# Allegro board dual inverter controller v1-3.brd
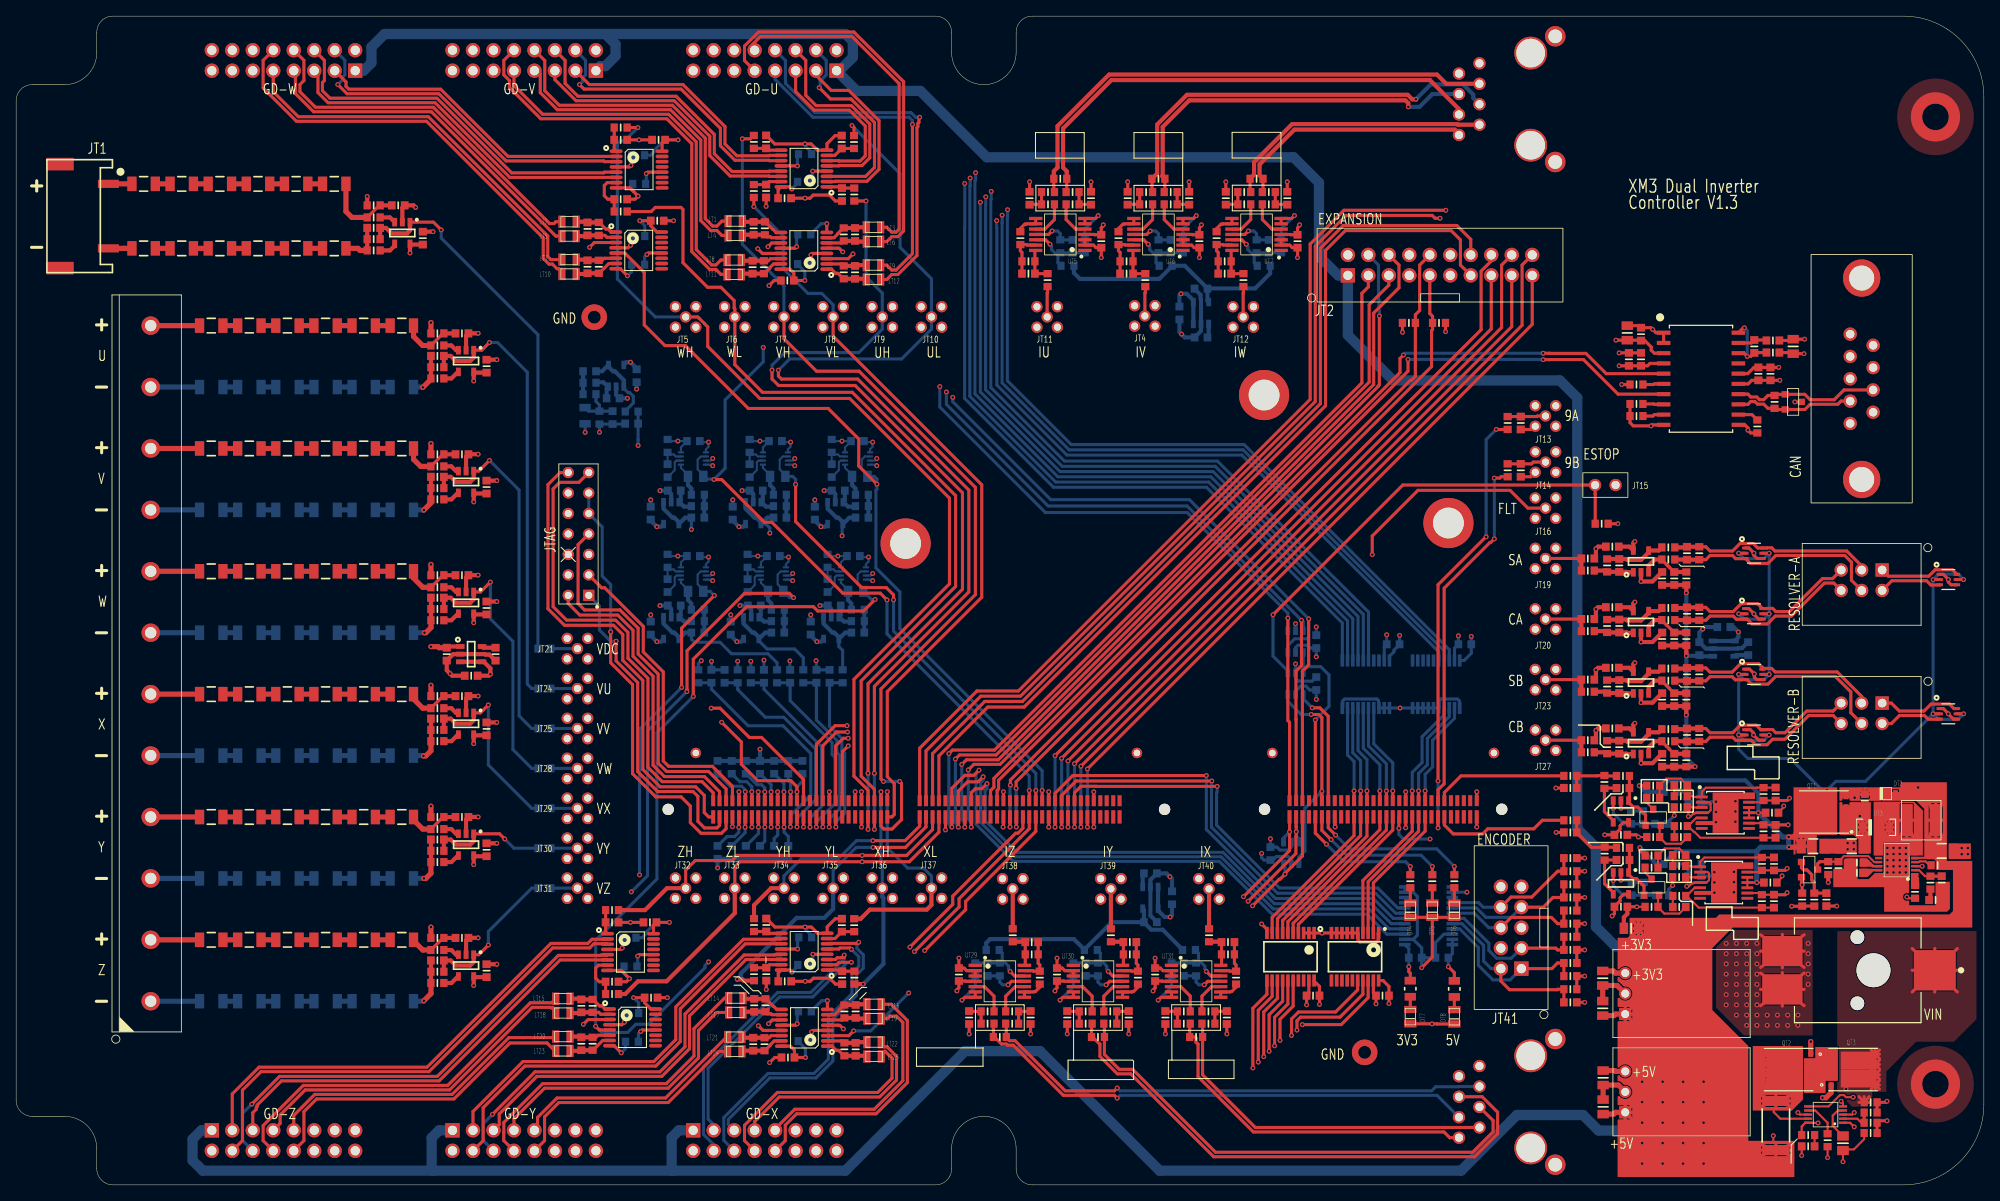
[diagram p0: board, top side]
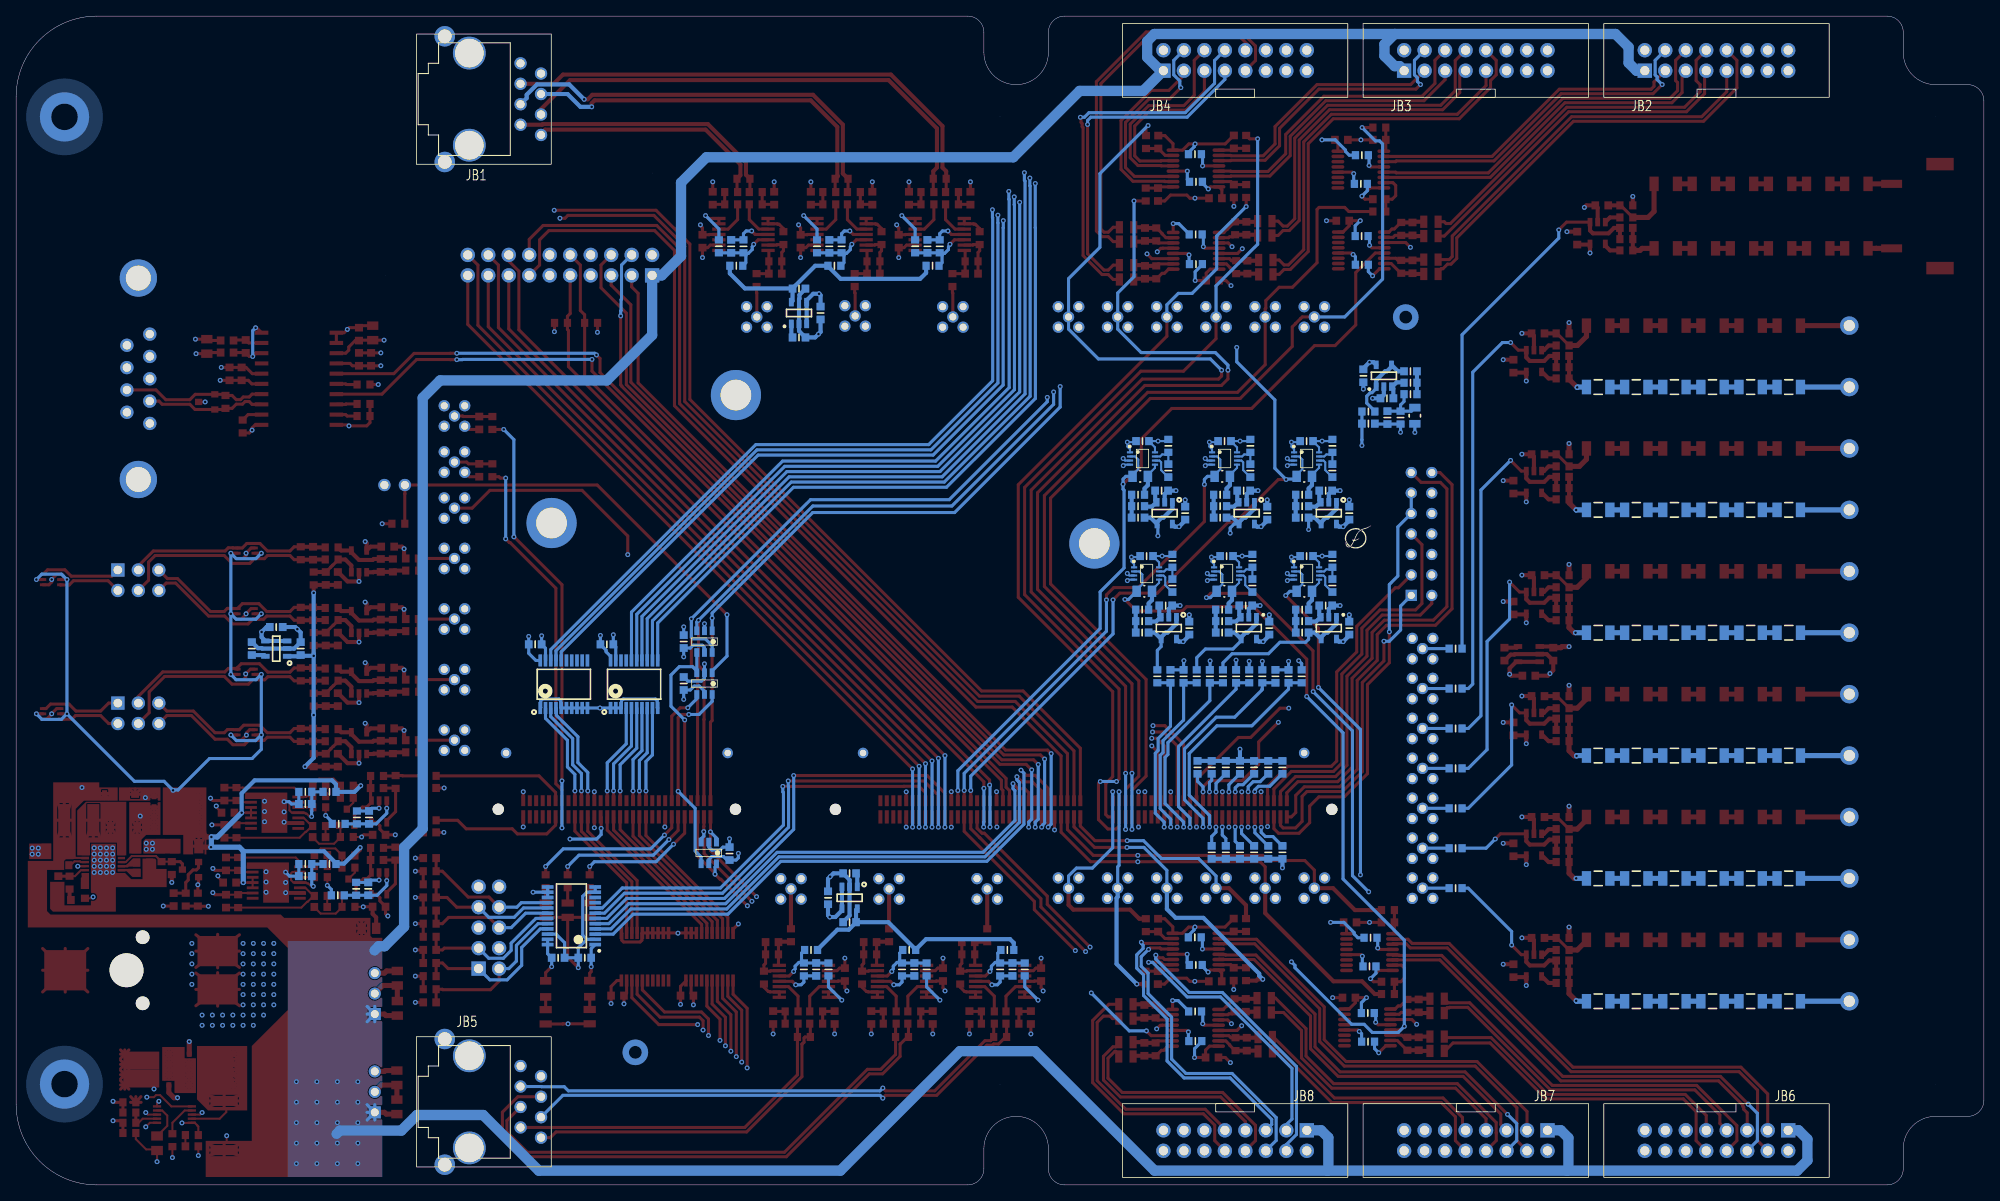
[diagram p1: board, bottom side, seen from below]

Outline 244 x 145 mm; copper layers: TOP, GND1, LAYER3, PWR, PWR2, BOTTOM. Coordinates in mm from the lower left corner of the outline.
Outline path: 0,134.5 arc(0.59,135.91) 2,136.5 6,136.5 arc(8.83,137.67) 10,140.5 10,143 arc(10.59,144.41) 12,145 114,145 arc(115.41,144.41) 116,143 116,140.5 arc(120,136.5) 124,140.5 124,143 arc(124.59,144.41) 126,145 234,145 arc(241.07,142.07) 244,135 244,10 arc(241.07,2.93) 234,0 126,0 arc(124.59,0.59) 124,2 124,4.5 arc(120,8.5) 116,4.5 116,2 arc(115.41,0.59) 114,0 12,0 arc(10.59,0.59) 10,2 10,4.5 arc(8.83,7.33) 6,8.5 2,8.5 arc(0.59,9.09) 0,10.5 0,134.5

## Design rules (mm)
constraint set DEFAULT: min track width 0.127
net group CANA: nets CANA-H CANA-L
net group COS-A-: nets COS-A-N COS-A-P
net group COS-B-: nets COS-B-N COS-B-P
net group CURRENT-U: nets CURRENT-U_N CURRENT-U_P
net group CURRENT-V: nets CURRENT-V_N CURRENT-V_P
net group CURRENT-W: nets CURRENT-W_N CURRENT-W_P
net group CURRENT-X: nets CURRENT-Z_N CURRENT-Z_P
net group CURRENT-Y: nets CURRENT-Y_N CURRENT-Y_P
net group CURRENT-Z: nets CURRENT-X_N CURRENT-X_P
net group EXC-A-: nets EXC-A-N EXC-A-P
net group EXC-B-: nets EXC-B-N EXC-B-P
net group SIN-A-: nets SIN-A-N SIN-A-P
net group SIN-B-: nets SIN-B-N SIN-B-P
net group U-FAULT-: nets U-FAULT-N U-FAULT-P
net group U-RTD-: nets U-RTD-N U-RTD-P
net group UHS-PWM-: nets UHS-PWM-N UHS-PWM-P
net group ULS-PWM-: nets ULS-PWM-N ULS-PWM-P
net group V-FAULT-: nets V-FAULT-N V-FAULT-P
net group V-RTD-: nets V-RTD-N V-RTD-P
net group VHS-PWM-: nets VHS-PWM-N VHS-PWM-P
net group VLS-PWM-: nets VLS-PWM-N VLS-PWM-P
net group W-FAULT-: nets W-FAULT-N W-FAULT-P
net group W-RTD-: nets W-RTD-N W-RTD-P
net group WHS-PWM-: nets WHS-PWM-N WHS-PWM-P
net group WLS-PWM-: nets WLS-PWM-N WLS-PWM-P
net group X-FAULT-: nets X-FAULT-N X-FAULT-P
net group X-RTD-: nets X-RTD-N X-RTD-P
net group XHS-PWM-: nets XHS-PWM-N XHS-PWM-P
net group XLS-PWM-: nets XLS-PWM-N XLS-PWM-P
net group Y-FAULT-: nets Y-FAULT-N Y-FAULT-P
net group Y-RTD-: nets Y-RTD-N Y-RTD-P
net group YHS-PWM-: nets YHS-PWM-N YHS-PWM-P
net group YLS-PWM-: nets YLS-PWM-N YLS-PWM-P
net group Z-FAULT-: nets Z-FAULT-N Z-FAULT-P
net group Z-RTD-: nets Z-RTD-N Z-RTD-P
net group ZHS-PWM-: nets ZHS-PWM-N ZHS-PWM-P
net group ZLS-PWM-: nets ZLS-PWM-N ZLS-PWM-P
net group VBM: nets N4927466 N4927468 N4927470 N4927528 N4927530 N4932900 N4932902 N4932904 N4932954 N4932956 V_V- V_Y-

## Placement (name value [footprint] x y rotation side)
CB1  100pF  [CAPC1608X90N]  131 116.44 270 bottom
CB2  100pF  [CAPC1608X90N]  143.17 116.44 270 bottom
CB3  100pF  [CAPC1608X90N]  155.34 116.44 270 bottom
CB4  0.1uF  [CAPC1608X87N]  146.92 111.19 180 bottom
CB5  0.1uF  [CAPC1608X87N]  144.25 108.17 270 bottom
CB6  0.1uF  [CAPC1608X87N]  146.92 105.14 180 bottom
CB7  10000pF  [CAPC1608X90N]  71.1 100.94 0 bottom
CB8  0.1uF  [CAPC1608X87N]  76.94 100.38 270 bottom
CB9  4700pF  [CAPC1608X90N]  74.02 97.59 180 bottom
CB10  100pF  [CAPC1608X90N]  73.96 95.19 90 bottom
CB11  4700pF  [CAPC1608X87N]  76.32 94.44 180 bottom
CB12  0.1uF  [CAPC1608X87N]  83.98 92.27 0 bottom
CB13  0.1uF  [CAPC1608X87N]  94.16 92.27 0 bottom
CB14  0.1uF  [CAPC1608X87N]  104.33 92.27 0 bottom
CB15  10000pF  [CAPC1608X90N]  80.78 88.61 270 bottom
CB16  10000pF  [CAPC1608X90N]  90.96 88.61 270 bottom
CB17  10000pF  [CAPC1608X90N]  101.13 88.61 270 bottom
CB18  10000pF  [CAPC1608X90N]  81.61 86.13 0 bottom
CB19  10000pF  [CAPC1608X90N]  91.78 86.13 0 bottom
CB20  10000pF  [CAPC1608X90N]  101.96 86.13 0 bottom
CB21  0.1uF  [CAPC1608X87N]  78.69 83.34 90 bottom
CB22  0.1uF  [CAPC1608X87N]  88.86 83.34 90 bottom
CB23  0.1uF  [CAPC1608X87N]  99.04 83.34 90 bottom
CB24  10000pF  [CAPC1608X90N]  84.53 82.78 180 bottom
CB25  10000pF  [CAPC1608X90N]  94.71 82.78 180 bottom
CB26  10000pF  [CAPC1608X90N]  104.88 82.78 180 bottom
CB27  0.1uF  [CAPC1608X87N]  83.98 78.01 0 bottom
CB28  0.1uF  [CAPC1608X87N]  93.9 78.01 0 bottom
CB29  0.1uF  [CAPC1608X87N]  103.82 78.01 0 bottom
CB30  10000pF  [CAPC1608X90N]  80.78 74.35 270 bottom
CB31  10000pF  [CAPC1608X90N]  90.7 74.35 270 bottom
CB32  10000pF  [CAPC1608X90N]  100.62 74.35 270 bottom
CB33  10000pF  [CAPC1608X90N]  81.61 71.87 0 bottom
CB34  10000pF  [CAPC1608X90N]  91.53 71.87 0 bottom
CB35  10000pF  [CAPC1608X90N]  101.45 71.87 0 bottom
CB36  0.1uF  [CAPC1608X87N]  211.74 69.21 180 bottom
CB37  0.1uF  [CAPC1608X87N]  78.69 69.08 90 bottom
CB38  0.1uF  [CAPC1608X87N]  88.61 69.08 90 bottom
CB39  0.1uF  [CAPC1608X87N]  98.53 69.08 90 bottom
CB40  10000pF  [CAPC1608X90N]  84.53 68.52 180 bottom
CB41  10000pF  [CAPC1608X90N]  94.45 68.52 180 bottom
CB42  10000pF  [CAPC1608X90N]  104.37 68.52 180 bottom
CB43  0.1uF  [CAPC1608X87N]  161.22 67.41 90 bottom
CB44  0.1uF  [CAPC1608X87N]  170.75 67.06 180 bottom
CB45  0.1uF  [CAPC1608X87N]  179.64 67.06 180 bottom
CB46  0.1uF  [CAPC1608X87N]  208.72 66.53 90 bottom
CB47  0.1uF  [CAPC1608X87N]  214.77 66.53 90 bottom
CB48  4700pF  [CAPC1608X87N]  86.22 63.1 90 bottom
CB49  4700pF  [CAPC1608X87N]  87.85 63.1 90 bottom
CB50  4700pF  [CAPC1608X87N]  92.73 63.1 90 bottom
CB51  4700pF  [CAPC1608X87N]  95.98 63.1 90 bottom
CB52  4700pF  [CAPC1608X87N]  99.24 63.1 90 bottom
CB53  4700pF  [CAPC1608X87N]  100.86 63.1 90 bottom
CB54  0.1uF  [CAPC1608X87N]  161.22 62.2 90 bottom
CB55  0.27 uF  [CAPC1608X90N]  86.98 51.8 90 bottom
CB56  0.27 uF  [CAPC1608X90N]  88.74 51.8 90 bottom
CB57  0.27 uF  [CAPC1608X90N]  90.49 51.8 90 bottom
CB58  0.27 uF  [CAPC1608X90N]  92.24 51.8 90 bottom
CB59  0.27 uF  [CAPC1608X90N]  94 51.8 90 bottom
CB60  0.27 uF  [CAPC1608X90N]  95.75 51.8 90 bottom
CB61  0.27 uF  [CAPC1608X90N]  97.51 51.8 90 bottom
CB62  0.27 uF  [CAPC1608X90N]  86.98 41.26 270 bottom
CB63  0.27 uF  [CAPC1608X90N]  88.74 41.26 270 bottom
CB64  0.27 uF  [CAPC1608X90N]  90.49 41.26 270 bottom
CB65  0.27 uF  [CAPC1608X90N]  92.24 41.26 270 bottom
CB66  0.27 uF  [CAPC1608X90N]  94 41.26 270 bottom
CB67  0.27 uF  [CAPC1608X90N]  95.75 41.26 270 bottom
CB68  0.1uF  [CAPC1608X87N]  155.54 41.1 90 bottom
CB69  0.1uF  [CAPC1608X87N]  140.65 38.65 0 bottom
CB70  0.1uF  [CAPC1608X87N]  143.33 35.62 90 bottom
CB71  0.1uF  [CAPC1608X87N]  140.65 32.59 0 bottom
CB72  0.1uF  [CAPC1608X87N]  173.49 28.18 0 bottom
CB73  0.1uF  [CAPC1608X87N]  176.79 28.18 180 bottom
CB74  100pF  [CAPC1608X90N]  120.46 26.73 90 bottom
CB75  100pF  [CAPC1608X90N]  132.63 26.73 90 bottom
CB76  100pF  [CAPC1608X90N]  144.79 26.73 90 bottom
CB79  0.1uF  [CAPC1608X87N]  208.14 38.3 0 bottom
CB81  0.1uF  [CAPC1608X87N]  208.14 47.26 0 bottom
CB83  0.1uF  [CAPC1608X87N]  200.34 36.73 90 bottom
CB84  0.1uF  [CAPC1608X87N]  200.24 45.59 90 bottom
CT1  100pF  [CAPC1608X90N]  74.97 129.65 0 top
CT2  0.1uF  [CAPC1608X87N]  79.66 129.65 180 top
CT3  100pF  [CAPC1608X90N]  93 129.4 90 top
CT4  100pF  [CAPC1608X90N]  102.37 129.38 90 top
CT5  100pF  [CAPC1608X90N]  93 123.3 270 top
CT6  100pF  [CAPC1608X90N]  102.41 122.87 270 top
CT7  0.1uF  [CAPC1608X87N]  95.29 122.41 0 top
CT8  100pF  [CAPC1608X90N]  125.67 122.41 90 top
CT9  100pF  [CAPC1608X90N]  133.29 122.41 270 top
CT10  100pF  [CAPC1608X90N]  137.83 122.41 90 top
CT11  100pF  [CAPC1608X90N]  145.45 122.41 270 top
CT12  100pF  [CAPC1608X90N]  150 122.41 90 top
CT13  100pF  [CAPC1608X90N]  157.62 122.41 270 top
CT14  100pF  [CAPC1608X90N]  74.97 122.28 0 top
CT15  4700pF  [CAPC1608X90N]  47.38 121.52 180 top
CT16  0.1uF  [CAPC1608X87N]  79.5 119.62 0 top
CT17  4700pF  [CAPC1608X90N]  44.33 118.73 0 top
CT18  27pF  [CAPC1608X90N]  91.45 118.68 90 top
CT19  27pF  [CAPC1608X90N]  70.85 118.6 90 top
CT20  27pF  [CAPC1608X90N]  104.02 117.92 90 top
CT21  0.1uF  [CAPC1608X87N]  50.43 117.46 90 top
CT22  0.1uF  [CAPC1608X87N]  134.56 117.08 270 top
CT23  0.1uF  [CAPC1608X87N]  146.72 117.08 270 top
CT24  0.1uF  [CAPC1608X87N]  158.89 117.08 270 top
CT25  27pF  [CAPC1608X90N]  70.85 113.9 270 top
CT26  27pF  [CAPC1608X90N]  91.32 113.85 270 top
CT27  27pF  [CAPC1608X90N]  104.02 113.22 270 top
CT28  100pF  [CAPC1608X90N]  125.52 113.05 0 top
CT29  100pF  [CAPC1608X90N]  137.69 113.05 0 top
CT30  100pF  [CAPC1608X90N]  149.86 113.05 0 top
CT31  0.1uF  [CAPC1608X87N]  95.63 112.2 180 top
CT33  0.1uF  [CAPC1608X87N]  199.98 102.42 90 top
CT34  10000pF  [CAPC1608X90N]  55.28 105.64 180 top
CT35  10000pF  [CAPC1608X90N]  52.24 102.84 0 top
CT36  0.1uF  [CAPC1608X87N]  58.33 101.57 90 top
CT37  1000 pF  [CAPC1608X90N]  186.57 94.52 270 top
CT39  10000pF  [CAPC1608X90N]  55.28 90.64 180 top
CT40  1000 pF  [CAPC1608X90N]  186.57 88.65 270 top
CT41  10000pF  [CAPC1608X90N]  52.24 87.84 0 top
CT42  0.1uF  [CAPC1608X87N]  58.33 86.57 90 top
CT43  0.1uF  [CAPC1608X87N]  197.93 79.18 180 top
CT44  47pF  [CAPC1608X87N]  207.18 78.36 90 top
CT45  1000 pF  [CAPC1608X90N]  194.89 77.71 0 top
CT46  330pF  [CAPC1608X87N]  198.78 76.85 270 top
CT47  10000pF  [CAPC1608X90N]  55.28 75.64 180 top
CT48  0.1uF  [CAPC1608X87N]  204.1 75.23 90 top
CT49  330pF  [CAPC1608X87N]  205.6 75.23 90 top
CT50  10000pF  [CAPC1608X90N]  52.24 72.84 0 top
CT51  0.1uF  [CAPC1608X87N]  197.93 71.66 180 top
CT52  0.1uF  [CAPC1608X87N]  58.33 71.57 90 top
CT53  47pF  [CAPC1608X87N]  207.18 70.85 90 top
CT54  1000 pF  [CAPC1608X90N]  194.89 70.2 0 top
CT55  330pF  [CAPC1608X87N]  198.78 69.34 270 top
CT56  0.1uF  [CAPC1608X87N]  204.1 67.72 90 top
CT57  330pF  [CAPC1608X87N]  205.6 67.72 90 top
CT58  0.1uF  [CAPC1608X87N]  53.4 65.85 270 top
CT59  0.1uF  [CAPC1608X87N]  59.45 65.85 270 top
CT60  0.1uF  [CAPC1608X87N]  197.93 64.15 180 top
CT61  47pF  [CAPC1608X87N]  207.18 63.33 90 top
CT62  0.1uF  [CAPC1608X87N]  56.42 63.17 180 top
CT63  1000 pF  [CAPC1608X90N]  194.89 62.68 0 top
CT64  330pF  [CAPC1608X87N]  198.78 61.82 270 top
CT65  10000pF  [CAPC1608X90N]  55.28 60.64 180 top
CT66  0.1uF  [CAPC1608X87N]  204.1 60.2 90 top
CT67  330pF  [CAPC1608X87N]  205.6 60.2 90 top
CT68  10000pF  [CAPC1608X90N]  52.24 57.84 0 top
CT69  0.1uF  [CAPC1608X87N]  197.93 56.63 180 top
CT70  0.1uF  [CAPC1608X87N]  58.33 56.57 90 top
CT71  47pF  [CAPC1608X87N]  207.18 55.82 90 top
CT72  1000 pF  [CAPC1608X90N]  194.89 55.17 0 top
CT73  330pF  [CAPC1608X87N]  198.78 54.3 270 top
CT74  0.1uF  [CAPC1608X87N]  204.1 52.69 90 top
CT75  330pF  [CAPC1608X87N]  205.6 52.69 90 top
CT81  10000pF  [CAPC1608X90N]  55.28 45.64 180 top
CT86  10000pF  [CAPC1608X90N]  52.24 42.84 0 top
CT87  10 uF  [CAPC3216X180N]  222.84 42.02 0 top
CT88  4.7uF  [CAPC3216X180N]  227.62 42.02 180 top
CT89  0.1uF  [CAPC1608X87N]  58.33 41.57 90 top
CT90  4.7uF  [CAPC3216X180N]  238.77 41.44 0 top
CT91  1000 pF  [CAPC1608X90N]  192.72 40.54 0 top
CT95  0.1uF  [CAPC1608X87N]  217.53 37.51 0 top
CT97  0.1uF  [CAPC1608X90N]  228.25 38.72 0 top
CT98  56 pF  [CAPC1608X90N]  238.77 37.5 90 top
CT99  1000 pF  [CAPC1608X90N]  192.72 35.66 0 top
CT100  100pF  [CAPC1608X90N]  224.47 35.39 270 top
CT103  1000 pF  [CAPC1608X87N]  192.72 43.73 0 top
CT104  1000pF  [CAPC1608X90N]  238.01 35.34 0 top
CT106  1000 pF  [CAPC1608X90N]  192.72 34.03 0 top
CT107  100pF  [CAPC1608X90N]  73.89 32.57 0 top
CT108  0.1uF  [CAPC1608X87N]  78.59 32.57 180 top
CT109  100pF  [CAPC1608X90N]  93.02 32.24 90 top
CT110  100pF  [CAPC1608X90N]  102.39 32.22 90 top
CT111  10uF  [CAPC2012X135N]  200.26 31.83 180 top
CT112  10000pF  [CAPC1608X90N]  55.28 30.64 180 top
CT113  100pF  [CAPC1608X90N]  125.93 30.12 180 top
CT114  100pF  [CAPC1608X90N]  138.1 30.12 180 top
CT115  100pF  [CAPC1608X90N]  150.27 30.12 180 top
CT116  1000 pF  [CAPC1608X90N]  192.72 29.15 0 top
CT117  10000pF  [CAPC1608X90N]  52.24 27.84 0 top
CT118  1000 pF  [CAPC1608X90N]  192.72 27.53 0 top
CT119  0.1uF  [CAPC1608X87N]  58.33 26.57 90 top
CT120  100pF  [CAPC1608X90N]  93.02 26.14 270 top
CT121  0.1uF  [CAPC1608X87N]  116.9 26.09 90 top
CT122  0.1uF  [CAPC1608X87N]  129.07 26.09 90 top
CT123  0.1uF  [CAPC1608X87N]  141.24 26.09 90 top
CT124  100pF  [CAPC1608X90N]  102.43 25.71 270 top
CT125  10uF  [CAPC2012X135N]  196.73 25.64 270 top
CT126  0.1uF  [CAPC1608X87N]  95.31 25.25 0 top
CT127  100pF  [CAPC1608X90N]  73.89 25.2 0 top
CT128  0.1uF  [CAPC1608X87N]  160.82 23.48 180 top
CT129  0.1uF  [CAPC1608X87N]  169.43 23.48 180 top
CT130  0.1uF  [CAPC1608X87N]  78.73 23.22 0 top
CT131  1000 pF  [CAPC1608X90N]  192.72 22.64 0 top
CT132  27pF  [CAPC1608X90N]  91.53 22.28 90 top
CT133  27pF  [CAPC1608X90N]  70.08 22.21 90 top
CT134  10uF  [CAPC2012X135N]  196.73 21.9 90 top
CT135  27pF  [CAPC1608X90N]  104.1 21.52 90 top
CT136  100pF  [CAPC1608X90N]  118.17 20.76 90 top
CT137  100pF  [CAPC1608X90N]  125.79 20.76 270 top
CT138  100pF  [CAPC1608X90N]  130.34 20.76 90 top
CT139  100pF  [CAPC1608X90N]  137.96 20.76 270 top
CT140  100pF  [CAPC1608X90N]  142.51 20.76 90 top
CT141  100pF  [CAPC1608X90N]  150.13 20.76 270 top
CT142  27pF  [CAPC1608X90N]  70.08 17.51 270 top
CT143  27pF  [CAPC1608X90N]  91.4 17.45 270 top
CT144  27pF  [CAPC1608X90N]  104.1 16.82 270 top
CT145  0.1uF  [CAPC1608X87N]  95.71 15.8 180 top
CT146  10uF  [CAPC2012X135N]  196.79 13.28 270 top
CT147  10uF  [CAPC2012X135N]  196.79 9.68 90 top
CT148  0.022uF  [CAPC2012X70N]  226.53 5.16 270 top
CT149  4700pF  [CAPC1608X90N]  222.21 4.78 180 top
CT150  0.1uF  [CAPC1608X87N]  201.49 105.55 90 top
CT151  0.1uF  [CAPC1608X87N]  217.54 100.62 270 top
CT152  0.1uF  [CAPC1608X87N]  215.53 104.02 270 top
CT153  10uF  [CAPC2012X135N]  199.78 105.7 90 top
CT154  10uF  [CAPC2012X135N]  220.35 104.02 270 top
CT155  10000pF  [CAPC1608X90N]  216.04 100.62 270 top
CT156  10000pF  [CAPC1608X90N]  201.48 102.42 90 top
CT157  18pF  [CAPC1608X90N]  217.98 39.82 270 top
CT158  18pF  [CAPC1608X90N]  217.97 35.2 90 top
CT159  1000 pF  [CAPC1608X90N]  199.25 40.31 0 top
CT160  0.1uF  [CAPC1608X87N]  198.99 34.51 0 top
CT161  0.1uF  [CAPC1608X87N]  217.73 46.17 0 top
CT162  18pF  [CAPC1608X90N]  218.18 48.49 270 top
CT163  0.1uF  [CAPC1608X87N]  198.99 43.43 0 top
CT164  1000 pF  [CAPC1608X87N]  192.72 49.24 0 top
CT165  1000 pF  [CAPC1608X90N]  199.25 49.23 0 top
CT166  18pF  [CAPC1608X90N]  218.17 43.87 90 top
CT167  10000pF  [CAPC1608X90N]  206.42 49.59 0 top
CT168  10000pF  [CAPC1608X90N]  206.43 43.14 0 top
CT169  10000pF  [CAPC1608X90N]  206.21 40.93 0 top
CT170  10000pF  [CAPC1608X90N]  206.23 34.48 0 top
DT2  CUS520,H3F  [SOD-323-AC]  231.91 48.55 180 top
DT3  NTS260ESFT3G  [SOD-123F-AC]  230.64 44.36 180 top
DT4  LH R974-LP-1  [D_0805]  172.88 34.08 270 top
DT5  LTST-C171KSKT  [D_0805]  175.61 34.08 270 top
DT6  LG R971-KN-1  [D_0805]  178.34 34.08 270 top
DT7  LTST-C171GKT  [D_0805]  172.88 20.87 270 top
DT8  LTST-C171GKT  [D_0805]  178.34 20.85 270 top
DT9  CPDT-12V  [SOT-23-3-D]  222.23 94.75 90 top
DT10  BAS40DW-04-TP  [SOT363_NEX]  215.49 55.82 0 top
DT11  BAS40DW-04-TP  [SOT363_NEX]  215.49 63.33 0 top
DT12  BAS40DW-04-TP  [SOT363_NEX]  239.59 58.44 0 top
DT13  BAS40DW-04-TP  [SOT363_NEX]  215.49 70.85 0 top
DT14  BAS40DW-04-TP  [SOT363_NEX]  215.49 78.36 0 top
DT15  BAS40DW-04-TP  [SOT363_NEX]  239.59 75.1 0 top
JB1  A-2014-2S-4-N-R  [RJ45_VERT_SHIELD_CON]  181.45 139.14 90 bottom
JB2  SBH11-PBPC-D08-ST-BK  [CON_2X8_SHROUDED_CORRECTED]  42.04 138.23 90 bottom
JB3  SBH11-PBPC-D08-ST-BK  [CON_2X8_SHROUDED_CORRECTED]  71.89 138.23 90 bottom
JB4  SBH11-PBPC-D08-ST-BK  [CON_2X8_SHROUDED_CORRECTED]  101.73 138.23 90 bottom
JB5  A-2014-2S-4-N-R  [RJ45_VERT_SHIELD_CON]  181.45 14.74 90 bottom
JB6  SBH11-PBPC-D08-ST-BK  [CON_2X8_SHROUDED_CORRECTED]  24.26 6.77 270 bottom
JB7  SBH11-PBPC-D08-ST-BK  [CON_2X8_SHROUDED_CORRECTED]  54.11 6.77 270 bottom
JB8  SBH11-PBPC-D08-ST-BK  [CON_2X8_SHROUDED_CORRECTED]  83.95 6.77 270 bottom
JT1  JST BH 8MM  [CON_JST-BHS-8MM-2PIN]  11.44 124.19 270 top
JT2  SBH11-PBPC-D10-ST-BK  [CON_2X10_SHROUDED]  176.57 114.11 90 top
JT3  CONN DSUB DE9  [CONN_DE9_M_VERT]  228.85 112.5 0 top
JT4  MMCX-J-P-H-ST-TH1  [MMCX_PLUG_TH]  139.96 107.81 90 top
JT5  MMCX-J-P-H-ST-TH1  [MMCX_PLUG_TH]  83.02 107.68 0 top
JT6  MMCX-J-P-H-ST-TH1  [MMCX_PLUG_TH]  89.12 107.68 0 top
JT7  MMCX-J-P-H-ST-TH1  [MMCX_PLUG_TH]  95.21 107.68 0 top
JT8  MMCX-J-P-H-ST-TH1  [MMCX_PLUG_TH]  101.31 107.68 0 top
JT9  MMCX-J-P-H-ST-TH1  [MMCX_PLUG_TH]  107.4 107.68 0 top
JT10  MMCX-J-P-H-ST-TH1  [MMCX_PLUG_TH]  113.5 107.68 0 top
JT11  MMCX-J-P-H-ST-TH1  [MMCX_PLUG_TH]  127.85 107.68 90 top
JT12  MMCX-J-P-H-ST-TH1  [MMCX_PLUG_TH]  152.16 107.68 90 top
JT13  MMCX-J-P-H-ST-TH1  [MMCX_PLUG_TH]  189.64 95.39 90 top
JT14  MMCX-J-P-H-ST-TH1  [MMCX_PLUG_TH]  189.64 89.68 90 top
JT15  IPL1-102-01-F-S-K  [CON_1X2_100MIL_TH]  195.79 86.83 0 top
JT16  MMCX-J-P-H-ST-TH1  [MMCX_PLUG_TH]  189.64 83.96 90 top
JT17  CON14  [JTAG]  69.73 80.75 180 top
JT18  61200621621  [A26815-ND]  221.48 79.59 270 top
JT19  MMCX-J-P-H-ST-TH1  [MMCX_PLUG_TH]  189.64 77.71 0 top
JT20  MMCX-J-P-H-ST-TH1  [MMCX_PLUG_TH]  189.64 70.2 0 top
JT21  MMCX-J-P-H-ST-TH1  [MMCX_PLUG_TH]  69.61 66.53 0 top
JT22  61200621621  [A26815-ND]  221.48 63.08 270 top
JT23  MMCX-J-P-H-ST-TH1  [MMCX_PLUG_TH]  189.64 62.68 0 top
JT24  MMCX-J-P-H-ST-TH1  [MMCX_PLUG_TH]  69.61 61.58 270 top
JT25  MMCX-J-P-H-ST-TH1  [MMCX_PLUG_TH]  69.61 56.62 270 top
JT26  F28379D-ControlCard  [F28379D_CONTROLCARD_CORRECTED]  111.63 55.58 180 top
JT27  MMCX-J-P-H-ST-TH1  [MMCX_PLUG_TH]  189.64 55.17 0 top
JT28  MMCX-J-P-H-ST-TH1  [MMCX_PLUG_TH]  69.61 51.67 270 top
JT29  MMCX-J-P-H-ST-TH1  [MMCX_PLUG_TH]  69.61 46.72 270 top
JT30  MMCX-J-P-H-ST-TH1  [MMCX_PLUG_TH]  69.61 41.77 270 top
JT31  MMCX-J-P-H-ST-TH1  [MMCX_PLUG_TH]  69.61 36.81 270 top
JT32  MMCX-J-P-H-ST-TH1  [MMCX_PLUG_TH]  83.02 36.81 0 top
JT33  MMCX-J-P-H-ST-TH1  [MMCX_PLUG_TH]  89.12 36.81 0 top
JT34  MMCX-J-P-H-ST-TH1  [MMCX_PLUG_TH]  95.21 36.81 0 top
JT35  MMCX-J-P-H-ST-TH1  [MMCX_PLUG_TH]  101.31 36.81 0 top
JT36  MMCX-J-P-H-ST-TH1  [MMCX_PLUG_TH]  107.4 36.81 0 top
JT37  MMCX-J-P-H-ST-TH1  [MMCX_PLUG_TH]  113.5 36.81 0 top
JT38  MMCX-J-P-H-ST-TH1  [MMCX_PLUG_TH]  123.58 36.72 0 top
JT39  MMCX-J-P-H-ST-TH1  [MMCX_PLUG_TH]  135.75 36.72 0 top
JT40  MMCX-J-P-H-ST-TH1  [MMCX_PLUG_TH]  147.92 36.72 0 top
JT41  SBH11-PBPC-D05-ST-BK  [CON_2X5_SHROUDED]  186.65 26.83 180 top
JT42  PJ-015AH-SMT  [CUI_PJ-015AH-SMT-TR]  230.31 26.63 270 top
JT43  1766877  [PHOENIX_1766877]  16.69 22.78 180 top
LT1  1uH  [L_0805]  89.16 119.57 0 top
LT2  1uH  [L_0805]  68.56 119.49 0 top
LT3  1uH  [L_0805]  106.31 118.8 180 top
LT4  1uH  [L_0805]  89.16 117.79 0 top
LT5  1uH  [L_0805]  68.56 117.71 0 top
LT6  1uH  [L_0805]  106.31 117.03 180 top
LT7  1uH  [L_0805]  68.56 114.79 0 top
LT8  1uH  [L_0805]  89.04 114.74 0 top
LT9  1uH  [L_0805]  106.31 114.11 180 top
LT10  1uH  [L_0805]  68.56 113.01 0 top
LT11  1uH  [L_0805]  89.04 112.96 0 top
LT12  1uH  [L_0805]  106.31 112.33 180 top
LT13  3.3uH  [IND-5040]  236.23 45.25 180 top
LT14  1uH  [L_0805]  89.24 23.17 0 top
LT15  1uH  [L_0805]  67.8 23.1 0 top
LT16  1uH  [L_0805]  106.39 22.41 180 top
LT17  1uH  [L_0805]  89.24 21.39 0 top
LT18  1uH  [L_0805]  67.8 21.32 0 top
LT19  1uH  [L_0805]  106.39 20.63 180 top
LT20  1uH  [L_0805]  67.8 18.4 0 top
LT21  1uH  [L_0805]  89.11 18.34 0 top
LT22  1uH  [L_0805]  106.39 17.71 180 top
LT23  1uH  [L_0805]  67.8 16.62 0 top
LT24  1uH  [L_0805]  89.11 16.57 0 top
LT25  1uH  [L_0805]  106.39 15.93 180 top
LT26  1000 Ohm  [INDC1608X95N]  217.84 104.76 0 top
LT27  1000 Ohm  [INDC1608X95N]  217.84 103.26 0 top
NOREF  -  []  238 12.5 90 top
NOREF#2  -  [unnamed#2]  6 132.5 0 top
NOREF#3  -  []  200.7 125.99 0 top
NOREF#4  -  [unnamed#2]  165.14 125.54 0 top
NOREF#5  -  [unnamed#2]  122 132.5 0 top
NOREF#6  -  []  0 72.5 0 top
NOREF#7  -  [unnamed#2]  6 12.5 0 top
NOREF#8  -  [unnamed#2]  198.16 112.84 0 top
NOREF#9  -  []  6 132.5 0 top
NOREF#10  -  []  63 0 90 top
NOREF#11  -  []  122 12.5 0 top
NOREF#12  -  []  6 12.5 0 top
NOREF#13  -  []  122 132.5 0 top
NOREF#14  -  [unnamed#2]  122 12.5 0 top
NOREF#15  -  []  79.24 78.94 180 bottom
QT1  SI7461DP  [POWER-SO8]  224.16 46.26 180 top
QT2  DMT6005LPS-13  [POWER-SO8]  219.8 14.31 180 top
QT3  DMT6005LPS-13  [POWER-SO8]  227.8 14.31 0 top
QT4  BC817-16LT3G  [SOT_23_3]  205.38 47.48 180 top
QT5  BC817-16LT3G  [SOT_23_3]  205.18 38.81 180 top
RB1  15k  [RESC1608X55N]  97.83 127.87 180 bottom
RB2  15k  [RESC1608X55N]  77.12 127.75 180 bottom
RB3  15k  [RESC1608X55N]  97.7 124.44 0 bottom
RB4  15k  [RESC1608X55N]  77.25 124.19 0 bottom
RB5  15k  [RESC1608X55N]  97.73 117.92 0 bottom
RB6  15k  [RESC1608X55N]  77.15 117.71 180 bottom
RB7  20k  [RESC1608X55N]  129.48 116.44 90 bottom
RB8  27k  [RESC1608X55N]  132.52 116.44 270 bottom
RB9  20k  [RESC1608X55N]  141.64 116.44 90 bottom
RB10  27k  [RESC1608X55N]  144.69 116.44 270 bottom
RB11  20k  [RESC1608X55N]  153.81 116.44 90 bottom
RB12  27k  [RESC1608X55N]  156.86 116.44 270 bottom
RB13  15k  [RESC1608X55N]  97.7 114.23 0 bottom
RB14  15k  [RESC1608X55N]  77.13 114.16 180 bottom
RB15  20k  [RESC1608X55N]  130.36 114.03 180 bottom
RB16  20k  [RESC1608X55N]  142.53 114.03 180 bottom
RB17  20k  [RESC1608X55N]  154.7 114.03 180 bottom
RB18  17.8k  [RESC1608X55N]  71.1 99.52 0 bottom
RB19  249 kOhm  [RESC3216X65N]  24.19 98.98 0 bottom
RB20  249 kOhm  [RESC3216X65N]  28.92 98.98 0 bottom
RB21  249 kOhm  [RESC3216X65N]  33.65 98.98 0 bottom
RB22  249 kOhm  [RESC3216X65N]  38.37 98.98 0 bottom
RB23  249 kOhm  [RESC3216X65N]  43.1 98.98 0 bottom
RB24  249 kOhm  [RESC3216X65N]  47.83 98.98 0 bottom
RB25  30.1k  [RESC1608X55N]  71.1 98.1 180 bottom
RB26  49.9  [RESC1608X55N]  76.32 95.94 0 bottom
RB27  10 kOhm  [RESC2012X60N]  70.56 95.43 270 bottom
RB28  10k  [RESC1608X65N]  72.33 95.19 90 bottom
RB29  2.2k  [RESC1608X55N]  80.78 91.68 270 bottom
RB30  2.2k  [RESC1608X55N]  90.96 91.68 270 bottom
RB31  2.2k  [RESC1608X55N]  101.13 91.68 270 bottom
RB32  0  [RESC2012X70N]  84.26 87.9 180 bottom
RB33  0  [RESC2012X70N]  94.44 87.9 180 bottom
RB34  0  [RESC2012X70N]  104.61 87.9 180 bottom
RB35  30.1k  [RESC1608X55N]  84.53 85.62 0 bottom
RB36  30.1k  [RESC1608X55N]  94.71 85.62 0 bottom
RB37  30.1k  [RESC1608X55N]  104.88 85.62 0 bottom
RB38  30.1k  [RESC1608X55N]  84.53 84.2 180 bottom
RB39  30.1k  [RESC1608X55N]  94.71 84.2 180 bottom
RB40  30.1k  [RESC1608X55N]  104.88 84.2 180 bottom
RB41  249 kOhm  [RESC3216X65N]  24.19 83.74 0 bottom
RB42  249 kOhm  [RESC3216X65N]  28.92 83.74 0 bottom
RB43  249 kOhm  [RESC3216X65N]  33.65 83.74 0 bottom
RB44  249 kOhm  [RESC3216X65N]  38.37 83.74 0 bottom
RB45  249 kOhm  [RESC3216X65N]  43.1 83.74 0 bottom
RB46  249 kOhm  [RESC3216X65N]  47.83 83.74 0 bottom
RB47  2.2k  [RESC1608X55N]  80.78 77.42 270 bottom
RB48  2.2k  [RESC1608X55N]  90.7 77.42 270 bottom
RB49  2.2k  [RESC1608X55N]  100.62 77.42 270 bottom
RB50  0  [RESC2012X70N]  84.26 73.64 180 bottom
RB51  0  [RESC2012X70N]  94.18 73.64 180 bottom
RB52  0  [RESC2012X70N]  104.1 73.64 180 bottom
RB53  30.1k  [RESC1608X55N]  84.53 71.36 0 bottom
RB54  30.1k  [RESC1608X55N]  94.45 71.36 0 bottom
RB55  30.1k  [RESC1608X55N]  104.37 71.36 0 bottom
RB56  30.1k  [RESC1608X55N]  84.53 69.94 180 bottom
RB57  30.1k  [RESC1608X55N]  94.45 69.94 180 bottom
RB58  30.1k  [RESC1608X55N]  104.37 69.94 180 bottom
RB59  249 kOhm  [RESC3216X65N]  24.19 68.5 0 bottom
RB60  249 kOhm  [RESC3216X65N]  28.92 68.5 0 bottom
RB61  249 kOhm  [RESC3216X65N]  33.65 68.5 0 bottom
RB62  249 kOhm  [RESC3216X65N]  38.37 68.5 0 bottom
RB63  249 kOhm  [RESC3216X65N]  43.1 68.5 0 bottom
RB64  249 kOhm  [RESC3216X65N]  47.83 68.5 0 bottom
RB65  49.9  [RESC1608X55N]  65.5 66.53 0 bottom
RB66  49.9  [RESC1608X55N]  84.59 63.1 270 bottom
RB67  49.9  [RESC1608X55N]  89.47 63.1 270 bottom
RB68  49.9  [RESC1608X55N]  91.1 63.1 270 bottom
RB69  49.9  [RESC1608X55N]  94.35 63.1 270 bottom
RB70  49.9  [RESC1608X55N]  97.61 63.1 270 bottom
RB71  49.9  [RESC1608X55N]  102.49 63.1 270 bottom
RB72  49.9  [RESC1608X55N]  65.5 61.58 0 bottom
RB73  49.9  [RESC1608X55N]  65.5 56.62 0 bottom
RB74  249 kOhm  [RESC3216X65N]  24.19 53.26 0 bottom
RB75  249 kOhm  [RESC3216X65N]  28.92 53.26 0 bottom
RB76  249 kOhm  [RESC3216X65N]  33.65 53.26 0 bottom
RB77  249 kOhm  [RESC3216X65N]  38.37 53.26 0 bottom
RB78  249 kOhm  [RESC3216X65N]  43.1 53.26 0 bottom
RB79  249 kOhm  [RESC3216X65N]  47.83 53.26 0 bottom
RB80  49.9  [RESC1608X55N]  65.5 51.67 0 bottom
RB81  49.9  [RESC1608X55N]  65.5 46.72 0 bottom
RB82  49.9  [RESC1608X55N]  65.5 41.77 0 bottom
RB83  249 kOhm  [RESC3216X65N]  24.19 38.02 0 bottom
RB84  249 kOhm  [RESC3216X65N]  28.92 38.02 0 bottom
RB85  249 kOhm  [RESC3216X65N]  33.65 38.02 0 bottom
RB86  249 kOhm  [RESC3216X65N]  38.37 38.02 0 bottom
RB87  249 kOhm  [RESC3216X65N]  43.1 38.02 0 bottom
RB88  249 kOhm  [RESC3216X65N]  47.83 38.02 0 bottom
RB89  49.9  [RESC1608X55N]  65.5 36.81 0 bottom
RB90  15k  [RESC1608X55N]  97.85 30.71 180 bottom
RB91  15k  [RESC1608X55N]  76.05 30.66 180 bottom
RB92  20k  [RESC1608X55N]  121.09 29.14 0 bottom
RB93  20k  [RESC1608X55N]  133.26 29.14 0 bottom
RB94  20k  [RESC1608X55N]  145.43 29.14 0 bottom
RB95  15k  [RESC1608X55N]  97.72 27.28 0 bottom
RB96  15k  [RESC1608X55N]  76.18 27.11 0 bottom
RB97  27k  [RESC1608X55N]  118.93 26.73 90 bottom
RB98  20k  [RESC1608X55N]  121.98 26.73 270 bottom
RB99  27k  [RESC1608X55N]  131.1 26.73 90 bottom
RB100  20k  [RESC1608X55N]  134.15 26.73 270 bottom
RB101  27k  [RESC1608X55N]  143.27 26.73 90 bottom
RB102  20k  [RESC1608X55N]  146.32 26.73 270 bottom
RB103  249 kOhm  [RESC3216X65N]  24.19 22.78 0 bottom
RB104  249 kOhm  [RESC3216X65N]  28.92 22.78 0 bottom
RB105  249 kOhm  [RESC3216X65N]  33.65 22.78 0 bottom
RB106  249 kOhm  [RESC3216X65N]  38.37 22.78 0 bottom
RB107  249 kOhm  [RESC3216X65N]  43.1 22.78 0 bottom
RB108  249 kOhm  [RESC3216X65N]  47.83 22.78 0 bottom
RB109  15k  [RESC1608X55N]  97.81 21.52 0 bottom
RB110  15k  [RESC1608X55N]  76.39 21.32 180 bottom
RB111  15k  [RESC1608X55N]  97.78 17.84 0 bottom
RB112  15k  [RESC1608X55N]  76.36 17.76 180 bottom
RB113  10k  [RESC1608X55N]  204.11 35.92 180 bottom
RB114  10k  [RESC1608X55N]  205.14 39.8 0 bottom
RB115  10k  [RESC1608X55N]  201.84 36.73 90 bottom
RB116  10k  [RESC1608X55N]  208.14 39.8 0 bottom
RB117  10k  [RESC1608X55N]  205.14 48.76 0 bottom
RB118  10k  [RESC1608X55N]  204 44.79 180 bottom
RB119  10k  [RESC1608X55N]  201.74 45.59 90 bottom
RB120  10k  [RESC1608X55N]  208.14 48.76 0 bottom
RT1  120  [RESC1608X55N]  74.97 131.17 180 top
RT2  120  [RESC1608X55N]  91.48 129.4 270 top
RT3  120  [RESC1608X55N]  103.9 129.38 270 top
RT4  120  [RESC1608X55N]  129.48 124.82 180 top
RT5  120  [RESC1608X55N]  141.64 124.82 180 top
RT6  120  [RESC1608X55N]  153.81 124.82 180 top
RT7  249 kOhm  [RESC3216X65N]  15.81 124.19 0 top
RT8  249 kOhm  [RESC3216X65N]  20.54 124.19 0 top
RT9  249 kOhm  [RESC3216X65N]  25.27 124.19 0 top
RT10  249 kOhm  [RESC3216X65N]  29.99 124.19 0 top
RT11  249 kOhm  [RESC3216X65N]  34.72 124.19 0 top
RT12  249 kOhm  [RESC3216X65N]  39.45 124.19 0 top
RT13  120  [RESC1608X55N]  91.48 123.3 90 top
RT14  2.7k  [RESC1608X55N]  127.95 123.17 180 top
RT15  2.7k  [RESC1608X55N]  131 123.17 0 top
RT16  2.7k  [RESC1608X55N]  140.12 123.17 180 top
RT17  2.7k  [RESC1608X55N]  143.17 123.17 0 top
RT18  2.7k  [RESC1608X55N]  152.29 123.17 180 top
RT19  2.7k  [RESC1608X55N]  155.34 123.17 0 top
RT20  120  [RESC1608X55N]  103.93 122.87 90 top
RT21  1k  [RESC1608X55N]  127.95 121.65 0 top
RT22  1k  [RESC1608X55N]  131 121.65 180 top
RT23  1k  [RESC1608X55N]  140.12 121.65 0 top
RT24  1k  [RESC1608X55N]  143.17 121.65 180 top
RT25  1k  [RESC1608X55N]  152.29 121.65 0 top
RT26  1k  [RESC1608X55N]  155.34 121.65 180 top
RT27  3.74 k  [RESC1608X55N]  44.33 121.52 0 top
RT28  120  [RESC1608X55N]  74.97 120.76 180 top
RT29  4.99k  [RESC1608X55N]  44.33 120.02 0 top
RT30  100  [RESC1608X55N]  92.85 118.68 90 top
RT31  100  [RESC1608X55N]  72.25 118.6 90 top
RT32  100  [RESC1608X55N]  102.63 117.92 90 top
RT33  27k  [RESC1608X55N]  124.52 117.46 270 top
RT34  27k  [RESC1608X55N]  136.69 117.46 270 top
RT35  27k  [RESC1608X55N]  148.86 117.46 270 top
RT36  3.74 k  [RESC1608X55N]  44.33 117.33 0 top
RT37  249 kOhm  [RESC3216X65N]  15.81 116.19 0 top
RT38  249 kOhm  [RESC3216X65N]  20.54 116.19 0 top
RT39  249 kOhm  [RESC3216X65N]  25.27 116.19 0 top
RT40  249 kOhm  [RESC3216X65N]  29.99 116.19 0 top
RT41  249 kOhm  [RESC3216X65N]  34.72 116.19 0 top
RT42  249 kOhm  [RESC3216X65N]  39.45 116.19 0 top
RT43  4.99k  [RESC1608X55N]  44.33 115.93 0 top
RT44  10k  [RESC1608X55N]  125.52 114.58 0 top
RT45  10k  [RESC1608X55N]  137.69 114.58 0 top
RT46  10k  [RESC1608X55N]  149.86 114.58 0 top
RT47  100  [RESC1608X55N]  72.25 113.9 270 top
RT48  100  [RESC1608X55N]  92.72 113.85 270 top
RT49  100  [RESC1608X55N]  102.63 113.22 270 top
RT50  49.9  [RESC1608X55N]  127.9 112.25 270 top
RT51  49.9  [RESC1608X55N]  140.02 112.25 270 top
RT52  49.9  [RESC1608X55N]  152.19 112.25 270 top
RT53  15k  [RESC1608X55N]  172.7 106.94 180 top
RT54  15k  [RESC1608X55N]  176.44 106.94 0 top
RT55  249 kOhm  [RESC3216X65N]  24.19 106.6 0 top
RT56  249 kOhm  [RESC3216X65N]  28.92 106.6 0 top
RT57  249 kOhm  [RESC3216X65N]  33.65 106.6 0 top
RT58  249 kOhm  [RESC3216X65N]  38.37 106.6 0 top
RT59  249 kOhm  [RESC3216X65N]  43.1 106.6 0 top
RT60  249 kOhm  [RESC3216X65N]  47.83 106.6 0 top
RT61  -  [RESC1608X55N]  52.24 105.64 0 top
RT62  4.99k  [RESC1608X55N]  52.24 104.14 0 top
RT64  -  [RESC1608X55N]  52.24 101.45 0 top
RT65  4.99k  [RESC1608X55N]  52.24 100.05 0 top
RT66  2k  [RESC1608X55N]  184.95 94.52 90 top
RT67  249 kOhm  [RESC3216X65N]  24.19 91.36 0 top
RT68  249 kOhm  [RESC3216X65N]  28.92 91.36 0 top
RT69  249 kOhm  [RESC3216X65N]  33.65 91.36 0 top
RT70  249 kOhm  [RESC3216X65N]  38.37 91.36 0 top
RT71  249 kOhm  [RESC3216X65N]  43.1 91.36 0 top
RT72  249 kOhm  [RESC3216X65N]  47.83 91.36 0 top
RT73  -  [RESC1608X55N]  52.24 90.64 0 top
RT74  4.99k  [RESC1608X55N]  52.24 89.14 0 top
RT75  2k  [RESC1608X55N]  184.95 88.65 90 top
RT76  -  [RESC1608X55N]  52.24 86.45 0 top
RT77  4.99k  [RESC1608X55N]  52.24 85.05 0 top
RT78  15k  [RESC1608X55N]  196.61 82.03 180 top
RT79  12.1K  [RESC1608X55N]  204.87 79.09 180 top
RT80  47k  [RESC1608X55N]  208.7 78.36 90 top
RT81  12.1K  [RESC1608X55N]  204.87 77.59 180 top
RT82  10k  [RESC1608X55N]  197.28 76.85 270 top
RT83  2k  [RESC1608X55N]  194.89 76.21 180 top
RT84  249 kOhm  [RESC3216X65N]  24.19 76.12 0 top
RT85  249 kOhm  [RESC3216X65N]  28.92 76.12 0 top
RT86  249 kOhm  [RESC3216X65N]  33.65 76.12 0 top
RT87  249 kOhm  [RESC3216X65N]  38.37 76.12 0 top
RT88  249 kOhm  [RESC3216X65N]  43.1 76.12 0 top
RT89  249 kOhm  [RESC3216X65N]  47.83 76.12 0 top
RT90  -  [RESC1608X55N]  52.24 75.64 0 top
RT91  10k  [RESC1608X55N]  207.1 75.23 270 top
RT92  4.99k  [RESC1608X55N]  52.24 74.14 0 top
RT93  12.1K  [RESC1608X55N]  204.87 71.57 180 top
RT94  -  [RESC1608X55N]  52.24 71.45 0 top
RT95  47k  [RESC1608X55N]  208.7 70.85 90 top
RT96  12.1K  [RESC1608X55N]  204.87 70.07 180 top
RT97  4.99k  [RESC1608X55N]  52.24 70.05 0 top
RT98  10k  [RESC1608X55N]  197.28 69.34 270 top
RT99  2k  [RESC1608X55N]  194.89 68.7 180 top
RT100  10k  [RESC1608X55N]  207.1 67.72 270 top
RT101  12.1K  [RESC1608X55N]  204.87 64.06 180 top
RT102  47k  [RESC1608X55N]  208.7 63.33 90 top
RT103  12.1K  [RESC1608X55N]  204.87 62.56 180 top
RT104  10k  [RESC1608X55N]  197.28 61.82 270 top
RT105  2k  [RESC1608X55N]  194.89 61.18 180 top
RT106  249 kOhm  [RESC3216X65N]  24.19 60.88 0 top
RT107  249 kOhm  [RESC3216X65N]  28.92 60.88 0 top
RT108  249 kOhm  [RESC3216X65N]  33.65 60.88 0 top
RT109  249 kOhm  [RESC3216X65N]  38.37 60.88 0 top
RT110  249 kOhm  [RESC3216X65N]  43.1 60.88 0 top
RT111  249 kOhm  [RESC3216X65N]  47.83 60.88 0 top
RT112  -  [RESC1608X55N]  52.24 60.64 0 top
RT113  10k  [RESC1608X55N]  207.1 60.2 270 top
RT114  4.99k  [RESC1608X55N]  52.24 59.14 0 top
RT115  12.1K  [RESC1608X55N]  204.87 56.54 180 top
RT116  -  [RESC1608X55N]  52.24 56.45 0 top
RT117  47k  [RESC1608X55N]  208.7 55.82 90 top
RT118  4.99k  [RESC1608X55N]  52.24 55.05 0 top
RT119  12.1K  [RESC1608X55N]  204.87 55.04 180 top
RT120  10k  [RESC1608X55N]  197.28 54.3 270 top
RT121  2k  [RESC1608X55N]  194.89 53.67 180 top
RT122  10k  [RESC1608X55N]  207.1 52.69 270 top
RT124  100k  [RESC1608X55N]  229.25 47.66 90 top
RT130  249 kOhm  [RESC3216X65N]  24.19 45.64 0 top
RT131  249 kOhm  [RESC3216X65N]  28.92 45.64 0 top
RT132  249 kOhm  [RESC3216X65N]  33.65 45.64 0 top
RT133  249 kOhm  [RESC3216X65N]  38.37 45.64 0 top
RT134  249 kOhm  [RESC3216X65N]  43.1 45.64 0 top
RT135  249 kOhm  [RESC3216X65N]  47.83 45.64 0 top
RT136  -  [RESC1608X55N]  52.24 45.64 0 top
RT137  4.99k  [RESC1608X55N]  52.24 44.14 0 top
RT141  -  [RESC1608X55N]  52.24 41.45 0 top
RT142  4.99k  [RESC1608X55N]  52.24 40.05 0 top
RT144  45.3k  [RESC1608X55N]  228.25 39.99 0 top
RT145  100k  [RESC1608X55N]  238.26 39.66 180 top
RT146  56k  [RESC1608X55N]  224.7 39.3 270 top
RT147  10k  [RESC1608X65N]  225.97 39.3 270 top
RT148  1k  [RESC1608X55N]  192.72 38.91 180 top
RT152  680  [RESC1608X55N]  172.88 37.67 270 top
RT153  680  [RESC1608X55N]  175.61 37.67 270 top
RT154  680  [RESC1608X55N]  178.34 37.67 270 top
RT155  10k  [RESC1608X65N]  237.37 37.5 270 top
RT156  1k  [RESC1608X55N]  192.72 37.29 180 top
RT159  165k  [RESC1608X55N]  235.47 36.36 270 top
RT160  10k  [RESC1608X65N]  221.47 35.39 90 top
RT161  120  [RESC1608X55N]  222.97 35.39 90 top
RT163  3.9k  [RESC1608X55N]  192.72 45.23 0 top
RT164  3.9k  [RESC1608X55N]  199.25 41.81 0 top
RT165  120  [RESC1608X55N]  73.89 34.09 180 top
RT166  1k  [RESC1608X55N]  192.72 32.41 180 top
RT167  120  [RESC1608X55N]  91.5 32.24 270 top
RT168  120  [RESC1608X55N]  103.92 32.22 270 top
RT169  49.9  [RESC1608X55N]  123.58 30.97 90 top
RT170  49.9  [RESC1608X55N]  135.75 30.97 90 top
RT171  49.9  [RESC1608X55N]  147.92 30.97 90 top
RT172  1k  [RESC1608X55N]  192.72 30.78 180 top
RT173  -  [RESC1608X55N]  52.24 30.64 0 top
RT174  249 kOhm  [RESC3216X65N]  24.19 30.4 0 top
RT175  249 kOhm  [RESC3216X65N]  28.92 30.4 0 top
RT176  249 kOhm  [RESC3216X65N]  33.65 30.4 0 top
RT177  249 kOhm  [RESC3216X65N]  38.37 30.4 0 top
RT178  249 kOhm  [RESC3216X65N]  43.1 30.4 0 top
RT179  249 kOhm  [RESC3216X65N]  47.83 30.4 0 top
RT180  4.99k  [RESC1608X55N]  52.24 29.14 0 top
RT181  10k  [RESC1608X55N]  125.93 28.59 180 top
RT182  10k  [RESC1608X55N]  138.1 28.59 180 top
RT183  10k  [RESC1608X55N]  150.27 28.59 180 top
RT184  -  [RESC1608X55N]  52.24 26.45 0 top
RT185  120  [RESC1608X55N]  91.5 26.14 90 top
RT186  1k  [RESC1608X55N]  192.72 25.9 180 top
RT187  27k  [RESC1608X55N]  126.94 25.71 90 top
RT188  27k  [RESC1608X55N]  139.1 25.71 90 top
RT189  27k  [RESC1608X55N]  151.27 25.71 90 top
RT190  120  [RESC1608X55N]  103.95 25.71 90 top
RT191  4.99k  [RESC1608X55N]  52.24 25.05 0 top
RT192  249  [RESC2012X60N]  172.88 24.34 270 top
RT193  499  [RESC2012X60N]  178.34 24.32 270 top
RT194  1k  [RESC1608X55N]  192.72 24.27 180 top
RT195  120  [RESC1608X55N]  73.89 23.68 180 top
RT196  100  [RESC1608X55N]  92.92 22.28 90 top
RT197  100  [RESC1608X55N]  71.48 22.21 90 top
RT198  1k  [RESC1608X55N]  120.46 21.52 0 top
RT199  1k  [RESC1608X55N]  123.51 21.52 180 top
RT200  1k  [RESC1608X55N]  132.63 21.52 0 top
RT201  1k  [RESC1608X55N]  135.67 21.52 180 top
RT202  1k  [RESC1608X55N]  144.79 21.52 0 top
RT203  1k  [RESC1608X55N]  147.84 21.52 180 top
RT204  100  [RESC1608X55N]  102.7 21.52 90 top
RT205  2.7k  [RESC1608X55N]  120.46 20 180 top
RT206  2.7k  [RESC1608X55N]  123.51 20 0 top
RT207  2.7k  [RESC1608X55N]  132.63 20 180 top
RT208  2.7k  [RESC1608X55N]  135.67 20 0 top
RT209  2.7k  [RESC1608X55N]  144.79 20 180 top
RT210  2.7k  [RESC1608X55N]  147.84 20 0 top
RT211  120  [RESC1608X55N]  121.98 18.35 0 top
RT212  120  [RESC1608X55N]  134.15 18.35 0 top
RT213  120  [RESC1608X55N]  146.32 18.35 0 top
RT214  100  [RESC1608X55N]  71.48 17.51 270 top
RT215  100  [RESC1608X55N]  92.8 17.45 270 top
RT216  100  [RESC1608X55N]  102.7 16.82 270 top
RT217  2.7 M  [RESC1608X55N]  229.96 10.24 0 top
RT218  2.7 M  [RESC1608X55N]  229.96 8.97 180 top
RT219  100k  [RESC1608X55N]  229.96 7.7 0 top
RT220  0.005  [RESC6432X70N]  218.21 7.37 270 top
RT221  200k  [RESC1608X55N]  229.96 6.43 180 top
RT222  22k  [RESC1608X55N]  222.21 6.18 180 top
RT223  100k  [RESC1608X55N]  224.62 5.55 90 top
RT224  120  [RESC1608X55N]  218.04 97.14 270 top
RT225  0.0  [RESC1608X65N]  200.92 99.3 180 top
RT226  0.0  [RESC1608X65N]  200.92 96.88 180 top
RT227  0.0  [RESC1608X65N]  200.92 95.38 180 top
RT228  0.0  [RESC1608X65N]  215.91 94.09 270 top
RT229  15k  [RESC1608X55N]  206.21 38.18 180 top
RT230  470k  [RESC1608X55N]  216.48 39.82 270 top
RT233  470k  [RESC1608X55N]  216.47 35.2 90 top
RT234  10k  [RESC1608X55N]  202.79 34.49 180 top
RT235  10k  [RESC1608X55N]  202.79 40.86 0 top
RT236  15k  [RESC1608X55N]  196.97 41.1 270 top
RT237  470k  [RESC1608X55N]  216.68 48.49 270 top
RT238  15k  [RESC1608X55N]  206.42 46.85 180 top
RT239  10k  [RESC1608X55N]  202.99 49.53 0 top
RT242  3.9k  [RESC1608X55N]  192.72 50.74 0 top
RT243  15k  [RESC1608X55N]  196.94 49.98 270 top
RT244  470k  [RESC1608X55N]  216.67 43.87 90 top
RT245  10k  [RESC1608X55N]  202.99 43.16 180 top
RT246  3.9k  [RESC1608X55N]  199.25 50.73 0 top
RT247  49.9k  [RESC1608X55N]  206.21 39.55 0 top
RT248  20  [RESC1608X55N]  202.79 39.36 180 top
RT249  49.9k  [RESC1608X55N]  206.23 35.85 0 top
RT250  49.9k  [RESC1608X55N]  206.42 48.22 0 top
RT251  20  [RESC1608X55N]  202.99 48.03 180 top
RT252  49.9k  [RESC1608X55N]  206.43 44.52 0 top
UB1  REF2030  [SOT23-5_0_95X2_70P_H1_45]  146.92 108.17 90 bottom
UB2  AD8615AUJZ-REEL7  [SOT23-5_0_95X2_70P_H1_22]  74.4 100.38 90 bottom
UB3  74LVC123  [VFSOP-8]  83.98 90.12 180 bottom
UB4  74LVC123  [VFSOP-8]  94.16 90.12 180 bottom
UB5  74LVC123  [VFSOP-8]  104.33 90.12 180 bottom
UB6  AD8615AUJZ-REEL7  [SOT23-5_0_95X2_70P_H1_22]  81.23 83.34 270 bottom
UB7  AD8615AUJZ-REEL7  [SOT23-5_0_95X2_70P_H1_22]  91.4 83.34 270 bottom
UB8  AD8615AUJZ-REEL7  [SOT23-5_0_95X2_70P_H1_22]  101.58 83.34 270 bottom
UB9  74LVC123  [VFSOP-8]  83.98 75.85 180 bottom
UB10  74LVC123  [VFSOP-8]  93.9 75.85 180 bottom
UB11  74LVC123  [VFSOP-8]  103.82 75.85 180 bottom
UB12  AD8615AUJZ-REEL7  [SOT23-5_0_95X2_70P_H1_22]  81.23 69.08 270 bottom
UB13  AD8615AUJZ-REEL7  [SOT23-5_0_95X2_70P_H1_22]  91.15 69.08 270 bottom
UB14  AD8615AUJZ-REEL7  [SOT23-5_0_95X2_70P_H1_22]  101.07 69.08 270 bottom
UB15  SN74LVC1G11DBVR  [SOT_23_6]  157.69 68.74 0 bottom
UB16  REF2030  [SOT23-5_0_95X2_70P_H1_45]  211.74 66.53 0 bottom
UB17  SN74LVC1G11DBVR  [SOT_23_6]  157.69 63.53 0 bottom
UB18  SN74LV541ATPWR  [SOP65P640X120-20AN]  167.37 62.11 90 bottom
UB19  SN74LV541ATPWR  [SOP65P640X120-20AN]  176.08 62.11 90 bottom
UB20  SN74LVC1G11DBVR  [SOT_23_6]  157.16 42.53 0 bottom
UB21  REF2030  [SOT23-5_0_95X2_70P_H1_45]  140.65 35.62 270 bottom
UB22  74LVC8T245  [SOP65P640X120-24N]  175.14 33.38 0 bottom
UT1  AM26LV31EIPWR  [TSSOP-16P_P65MM]  97.7 126.09 180 top
UT2  AM26LV31EIPWR  [TSSOP-16P_P65MM]  77.25 125.97 0 top
UT3  AD8615AUJZ-REEL7  [SOT23-5_0_95X2_70P_H1_22]  47.89 118.09 270 top
UT4  AM26LV32EIPWR  [TSSOP-16P_P65MM]  77.2 115.93 0 top
UT5  AD8618ARUZ-REEL  [TSSOP-14]  132.52 115.93 180 top
UT6  AD8618ARUZ-REEL  [TSSOP-14]  144.69 115.93 180 top
UT7  AD8618ARUZ-REEL  [TSSOP-14]  156.86 115.93 180 top
UT8  AM26LV32EIPWR  [TSSOP-16P_P65MM]  97.67 115.88 180 top
UT10  AD8615AUJZ-REEL7  [SOT23-5_0_95X2_70P_H1_22]  55.79 102.21 270 top
UT11  AD8615AUJZ-REEL7  [SOT23-5_0_95X2_70P_H1_22]  55.79 87.21 270 top
UT13  AD8615AUJZ-REEL7  [SOT23-5_0_95X2_70P_H1_22]  201.48 77.35 90 top
UT14  AD8615AUJZ-REEL7  [SOT23-5_0_95X2_70P_H1_22]  55.79 72.21 270 top
UT15  AD8615AUJZ-REEL7  [SOT23-5_0_95X2_70P_H1_22]  201.48 69.84 90 top
UT16  REF2030  [SOT23-5_0_95X2_70P_H1_45]  56.42 65.85 0 top
UT17  AD8615AUJZ-REEL7  [SOT23-5_0_95X2_70P_H1_22]  201.48 62.32 90 top
UT18  AD8615AUJZ-REEL7  [SOT23-5_0_95X2_70P_H1_22]  55.79 57.21 270 top
UT19  AD8615AUJZ-REEL7  [SOT23-5_0_95X2_70P_H1_22]  201.48 54.8 90 top
UT21  AD8615AUJZ-REEL7  [SOT23-5_0_95X2_70P_H1_22]  55.79 42.21 270 top
UT22  LT3581  [MSOP-16-EP]  233.18 40.29 180 top
UT24  BSS138L  [SOT_23_3]  224.25 36.73 90 top
UT25  AM26LV31EIPWR  [TSSOP-16P_P65MM]  97.72 28.94 180 top
UT26  AM26LV31EIPWR  [TSSOP-16P_P65MM]  76.18 28.88 0 top
UT27  SN74LV541ATPWR  [SOP65P640X120-20AN]  158.02 28.3 270 top
UT28  SN74LV541ATPWR  [SOP65P640X120-20AN]  166.02 28.3 270 top
UT29  AD8618ARUZ-REEL  [TSSOP-14]  118.93 27.24 0 top
UT30  AD8618ARUZ-REEL  [TSSOP-14]  131.1 27.24 0 top
UT31  AD8618ARUZ-REEL  [TSSOP-14]  143.27 27.24 0 top
UT32  AD8615AUJZ-REEL7  [SOT23-5_0_95X2_70P_H1_22]  55.79 27.21 270 top
UT33  OKI-78SR-3.3  [OKI-78SR-H]  199.53 23.73 180 top
UT34  AM26LV32EIPWR  [TSSOP-16P_P65MM]  76.43 19.54 0 top
UT35  AM26LV32EIPWR  [TSSOP-16P_P65MM]  97.75 19.49 180 top
UT36  OKI-78SR-5  [OKI-78SR-H]  199.53 11.54 180 top
UT37  LTC4368IMS-2#PBF  [MSOP_10]  226.53 7.7 180 top
UT38  ADM3057EBRWZ  [RW-20_ADI]  208.93 100.01 0 top
UT39  AD8615AUJZ-REEL7  [SOT23-5_0_95X2_70P_H1_22]  198.99 37.41 270 top
UT40  AD8615AUJZ-REEL7  [SOT23-5_0_95X2_70P_H1_22]  198.99 46.33 270 top
UT41  ALM2402FQPWPRQ1  [HTSSOP14_5X4P4_TEX]  211.75 37.51 0 top
UT43  ALM2402FQPWPRQ1  [HTSSOP14_5X4P4_TEX]  211.95 46.17 0 top

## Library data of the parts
CB1-CB76 CB79 CB81 CB83 CB84 CT1-CT31 CT33-CT37 CT39-CT75 CT81 CT86-CT91 CT95 CT97-CT100 CT103 CT104 CT106-CT170 = CAP
DT2 = DIODE_SCHOTTKY_C2_A1_0
DT3 = DIODE_SCHOTTKY_0
DT4-DT8 = LED_0
DT9 = DIODE_TVS_DUAL
DT10-DT15 = DIODE_QUAD_A1_C2_C1A2: User Part Number: TMP-1744; Tolerance: TOL
JB1 JB5 = ModularJack8P8C-shielded
JB2-JB4 JB6-JB8 = CON16A_Corrected
JT1 JT15 = CON2
JT2 = CON20A
JT3 = CONN DSUB DE9
JT4-JT14 JT16 JT19-JT21 JT23-JT25 JT27-JT40 = BNC_5P
JT17 = CON14A
JT18 JT22 = HEADER 3X2
JT26 = F28379D-ControlCard_1
JT41 = HDR_2X5_M
JT42 = PJ-015AH-SMT-TR
JT43 = 12 HEADER
LT1-LT12 LT14-LT25 = INDUCTOR
LT13 = IND
LT26 LT27 = IND_FB
QT1 = MOSFET_P_PSO8: User Part Number: TMP-1595; Tolerance: TOL
QT2 QT3 = MOSFET_N_PSO8: User Part Number: TMP-1530; Tolerance: TOL
QT4 QT5 = BJT_NPN_BEC
RB1-RB6 RB13 RB14 RB28 RB90 RB91 RB95 RB96 RB109-RB112 RT1-RT3 RT13 RT20-RT26 RT28 RT53 RT54 RT78 RT124 RT145-RT148 RT155 RT156 RT160 RT161 RT165-RT168 RT172 RT185 RT186 RT190 RT192-RT195 RT198-RT203 RT217-RT219 RT221-RT229 RT236 RT238 RT243 = R
RB7-RB12 RB15-RB26 RB29-RB31 RB35-RB49 RB53-RB89 RB92-RB94 RB97-RB108 RB113-RB120 RT7-RT12 RT14-RT19 RT27 RT29-RT52 RT55-RT60 RT62 RT65-RT72 RT74 RT75 RT77 RT79-RT89 RT91-RT93 RT95-RT111 RT113-RT115 RT117-RT122 RT130-RT135 RT137 RT142 RT144 RT152-RT154 RT159 RT163 RT164 RT169-RT171 RT174-RT183 RT187-RT189 RT191 RT196 RT197 RT204-RT210 RT214-RT216 RT220 RT230 RT233-RT235 RT237 RT239 RT242 RT244-RT252 = RES
RB27 = PTC
RB32-RB34 RB50-RB52 RT4-RT6 RT211-RT213 = RES_0
RT61 RT64 RT73 RT76 RT90 RT94 RT112 RT116 RT136 RT141 RT173 RT184 = RES_RESC1608X55N_DISCRETE_1.8 K
UB1 UB16 UB21 UT16 = REF2030
UB2 UB6-UB8 UB12-UB14 UT3 UT10 UT11 UT13-UT15 UT17-UT19 UT21 UT32 UT39 UT40 = AD8615
UB3-UB5 UB9-UB11 = 74LVC123
UB15 UB17 UB20 = AND3_1X_6PIN
UB18 UB19 UT27 UT28 = 74-541_20P
UB22 = 74LVC8T245
UT1 UT2 UT25 UT26 = DIFFDRVR_4X_16P
UT4 UT8 UT34 UT35 = DIFFRCVR_4XG_16P
UT5-UT7 UT29-UT31 = OPAMP_4X_14P
UT22 = LT3581
UT24 = MOSFET_N_GSD
UT33 UT36 = LM7805
UT37 = LTC4368
UT38 = ADM3057EBRWZ: User Part Number: TMP-1749; Tolerance: TOL
UT41 UT43 = ALM2402FQPWPRQ1: User Part Number: TMP-1745; Tolerance: TOL

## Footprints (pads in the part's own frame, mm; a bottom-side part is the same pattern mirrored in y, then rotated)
A26815-ND
  rect 1.651x1.651 hole 1.067: 1(3.302,9.906)
  round 1.651 hole 1.067: 2(5.842,9.906) 3(3.302,7.366) 4(5.842,7.366) 5(3.302,4.826) 6(5.842,4.826)
CAPC1608X87N
  rect 0.95x1 smd: 1(-0.8,0) 2(0.8,0)
CAPC1608X90N
  rect 0.95x1 smd: 1(-0.8,0) 2(0.8,0)
CAPC2012X70N
  rect 1.15x1.45 smd: 1(-0.9,0) 2(0.9,0)
CAPC2012X135N
  rect 1.05x1.4 smd: 1(-0.9,0) 2(0.9,0)
CAPC3216X180N
  rect 1.15x1.8 smd: 1(-1.5,0) 2(1.5,0)
CON_1X2_100MIL_TH
  round 1.524 hole 1.016: 1(0,0) 2(2.54,0)
CON_2X5_SHROUDED
  rect 1.778x1.778 hole 1.143: 1(0,0)
  round 1.778 hole 1.143: 2(2.54,0) 3(0,-2.54) 4(2.54,-2.54) 5(0,-5.08) 6(2.54,-5.08) 7(0,-7.62) 8(2.54,-7.62) 9(0,-10.16) 10(2.54,-10.16)
CON_2X8_SHROUDED_CORRECTED
  rect 1.778x1.778 hole 1.143: 1(0,0)
  round 1.778 hole 1.143: 2(2.54,0) 3(0,-2.54) 4(2.54,-2.54) 5(0,-5.08) 6(2.54,-5.08) 7(0,-7.62) 8(2.54,-7.62) 9(0,-10.16) 10(2.54,-10.16) 11(0,-12.7) 12(2.54,-12.7) 13(0,-15.24) 14(2.54,-15.24) 15(0,-17.78) 16(2.54,-17.78)
CON_2X10_SHROUDED
  rect 1.778x1.778 hole 1.143: 1(-1.27,11.43)
  round 1.778 hole 1.143: 2(1.27,11.43) 3(-1.27,8.89) 4(1.27,8.89) 5(-1.27,6.35) 6(1.27,6.35) 7(-1.27,3.81) 8(1.27,3.81) 9(-1.27,1.27) 10(1.27,1.27) 11(-1.27,-1.27) 12(1.27,-1.27) 13(-1.27,-3.81) 14(1.27,-3.81) 15(-1.27,-6.35) 16(1.27,-6.35) 17(-1.27,-8.89) 18(1.27,-8.89) 19(-1.27,-11.43) 20(1.27,-11.43)
CON_JST-BHS-8MM-2PIN
  rect 1.55x3.4 smd: (-2.45,-6) (10.45,-6)
  rect 1x2.6 smd: 1(0,0) 2(8,0)
CONN_DE9_M_VERT
  round 1.651 hole 1.041: 1(-1.42,-18.035) 2(-1.42,-15.265) 3(-1.42,-12.495) 4(-1.42,-9.725) 5(-1.42,-6.955) 6(1.42,-16.65) 7(1.42,-13.88) 8(1.42,-11.11) 9(1.42,-8.34)
  round 4.623 hole 3.099: 10(0,-24.99) 11(0,0)
CUI_PJ-015AH-SMT-TR
  round 1.7 hole 1.7 unplated: (-4.1,-2) (4.1,-2)
  round 4.2 hole 4.2 unplated: (0,0)
  rect 5x5.2 smd: 1(0,7.6)
  rect 3.75x5 smd: 2(-2.375,-11.3) 3(2.375,-11.3)
D_0805
  rect 0.889x1.524 smd: 1(-0.889,0) 2(0.889,0)
F28379D_CONTROLCARD_CORRECTED
  round 1.4 hole 1.4 unplated: (-72.584,8.985) (-43.171,8.985) (-30.775,9) (30.775,9)
  round 6.223 hole 3.81: (-65.975,-26.529) (-43.115,-42.404) (1.335,-23.989)
  rect 0.5x1.65 smd: 1(25.197,9.931) 3(24.409,9.931) 5(23.597,9.931) 7(22.809,9.931) 9(21.996,9.931) 11(21.209,9.931) 13(20.396,9.931) 15(19.609,9.931) 17(18.796,9.931) 19(18.009,9.931) 21(17.196,9.931) 23(16.408,9.931) 25(15.596,9.931) 27(14.808,9.931) 29(13.995,9.931) 31(13.208,9.931) 33(12.395,9.931) 35(11.608,9.931) 37(10.795,9.931) 39(10.008,9.931) 41(9.195,9.931) 43(8.407,9.931) 45(7.595,9.931) 47(6.807,9.931) 49(5.994,9.931) 51(5.207,9.931) 53(4.394,9.931) 55(3.607,9.931) 57(-0.406,9.931) 59(-1.194,9.931) 61(-2.007,9.931) 63(-2.794,9.931) 65(-3.607,9.931) 67(-4.394,9.931) 69(-5.207,9.931) 71(-5.994,9.931) 73(-6.807,9.931) 75(-7.595,9.931) 77(-8.407,9.931) 79(-9.195,9.931) 81(-10.008,9.931) 83(-10.795,9.931) 85(-11.608,9.931) 87(-12.395,9.931) 89(-13.208,9.931) 91(-13.995,9.931) 93(-14.808,9.931) 95(-15.596,9.931) 97(-16.408,9.931) 99(-17.196,9.931) 101(-18.009,9.931) 103(-18.796,9.931) 105(-19.609,9.931) 107(-20.396,9.931) 109(-21.209,9.931) 111(-21.996,9.931) 113(-22.809,9.931) 115(-23.597,9.931) 117(-24.409,9.931) 119(-25.197,9.931) 121(-46.27,9.925) 123(-47.083,9.925) 125(-47.87,9.925) 127(-48.683,9.925) 129(-49.47,9.925) 131(-50.283,9.925) 133(-51.071,9.925) 135(-51.883,9.925) 137(-52.671,9.925) 139(-53.484,9.925) 141(-54.271,9.925) 143(-55.084,9.925) 145(-55.871,9.925) 147(-56.684,9.925) 149(-57.471,9.925) 151(-58.284,9.925) 153(-59.072,9.925) 155(-59.884,9.925) 157(-60.672,9.925) 159(-61.485,9.925) 161(-62.272,9.925) 163(-63.085,9.925) 165(-63.872,9.925) 167(-64.685,9.925) 169(-65.472,9.925) 171(-66.285,9.925) 173(-67.073,9.925) 175(-67.885,9.925) 177(-68.673,9.925) 179(-69.486,9.925)
  rect 0.5x1.35 smd: 2(25.197,7.925) 4(24.409,7.925) 6(23.597,7.925) 8(22.809,7.925) 10(21.996,7.925) 12(21.209,7.925) 14(20.396,7.925) 16(19.609,7.925) 18(18.796,7.925) 20(18.009,7.925) 22(17.196,7.925) 24(16.408,7.925) 26(15.596,7.925) 28(14.808,7.925) 30(13.995,7.925) 32(13.208,7.925) 34(12.395,7.925) 36(11.608,7.925) 38(10.795,7.925) 40(10.008,7.925) 42(9.195,7.925) 44(8.407,7.925) 46(7.595,7.925) 48(6.807,7.925) 50(5.994,7.925) 52(5.207,7.925) 54(4.394,7.925) 56(3.607,7.925) 58(-0.406,7.925) 60(-1.194,7.925) 62(-2.007,7.925) 64(-2.794,7.925) 66(-3.607,7.925) 68(-4.394,7.925) 70(-5.207,7.925) 72(-5.994,7.925) 74(-6.807,7.925) 76(-7.595,7.925) 78(-8.407,7.925) 80(-9.195,7.925) 82(-10.008,7.925) 84(-10.795,7.925) 86(-11.608,7.925) 88(-12.395,7.925) 90(-13.208,7.925) 92(-13.995,7.925) 94(-14.808,7.925) 96(-15.596,7.925) 98(-16.408,7.925) 100(-17.196,7.925) 102(-18.009,7.925) 104(-18.796,7.925) 106(-19.609,7.925) 108(-20.396,7.925) 110(-21.209,7.925) 112(-21.996,7.925) 114(-22.809,7.925) 116(-23.597,7.925) 118(-24.409,7.925) 120(-25.197,7.925) 122(-46.27,7.918) 124(-47.083,7.918) 126(-47.87,7.918) 128(-48.683,7.918) 130(-49.47,7.918) 132(-50.283,7.918) 134(-51.071,7.918) 136(-51.883,7.918) 138(-52.671,7.918) 140(-53.484,7.918) 142(-54.271,7.918) 144(-55.084,7.918) 146(-55.871,7.918) 148(-56.684,7.918) 150(-57.471,7.918) 152(-58.284,7.918) 154(-59.072,7.918) 156(-59.884,7.918) 158(-60.672,7.918) 160(-61.485,7.918) 162(-62.272,7.918) 164(-63.085,7.918) 166(-63.872,7.918) 168(-64.685,7.918) 170(-65.472,7.918) 172(-66.285,7.918) 174(-67.073,7.918) 176(-67.885,7.918) 178(-68.673,7.918) 180(-69.486,7.918)
  round 1.3 hole 0.81: G1(-27.35,2) G2(27.35,2) G3(-44.136,2) G4(-71.619,2)
HTSSOP14_5X4P4_TEX
  rect 1.46x0.356 smd: 1(-2.927,1.95) 2(-2.927,1.3) 3(-2.927,0.65) 4(-2.927,0) 5(-2.927,-0.65) 6(-2.927,-1.3) 7(-2.927,-1.95) 8(2.927,-1.95) 9(2.927,-1.3) 10(2.927,-0.65) 11(2.927,0) 12(2.927,0.65) 13(2.927,1.3) 14(2.927,1.95)
  rect 1.397x2.438 smd: EPAD(0,0)
IND-5040
  rect 1.5x4 smd: 1(-1.8,0) 2(1.8,0)
INDC1608X95N
  rect 0.95x1 smd: 1(-0.8,0) 2(0.8,0)
JTAG
  rect 1.397x1.397 hole 0.889: 1(-1.27,7.62)
  round 1.397 hole 0.889: 2(1.27,7.62) 3(-1.27,5.08) 4(1.27,5.08) 5(-1.27,2.54) 6(1.27,2.54) 7(-1.27,0) 8(1.27,0) 9(-1.27,-2.54) 10(1.27,-2.54) 11(-1.27,-5.08) 12(1.27,-5.08) 13(-1.27,-7.62) 14(1.27,-7.62)
L_0805
  rect 0.889x1.524 smd: 1(-0.889,0) 2(0.889,0)
MMCX_PLUG_TH
  round 1.397 hole 0.889: 1(0,0) 2(-1.27,1.27) 3(1.27,1.27) 4(1.27,-1.27) 5(-1.27,-1.27)
MSOP-16-EP
  rect 0.9x0.3 smd: 1(-2.235,1.751) 2(-2.235,1.251) 3(-2.235,0.751) 4(-2.235,0.25) 5(-2.235,-0.25) 6(-2.235,-0.751) 7(-2.235,-1.251) 8(-2.235,-1.751) 9(2.235,-1.751) 10(2.235,-1.251) 11(2.235,-0.751) 12(2.235,-0.25) 13(2.235,0.25) 14(2.235,0.751) 15(2.235,1.251) 16(2.235,1.751)
  rect 1.651x3.048 smd: 17(0,0)
MSOP_10
  rect 1.016x0.305 smd: 1(0,0) 2(0,-0.508) 3(0,-1.016) 4(0,-1.524) 5(0,-2.032) 6(4.318,-2.032) 7(4.318,-1.524) 8(4.318,-1.016) 9(4.318,-0.508) 10(4.318,0)
